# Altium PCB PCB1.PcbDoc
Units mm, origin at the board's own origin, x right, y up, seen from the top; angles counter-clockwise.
Board outline 84.33 x 62.74 mm, 2 copper layers (Top Layer, Bottom Layer); 29 components, 23 nets, 114 pads, 0 vias.
Unrouted connection lines stored in the file: 67.
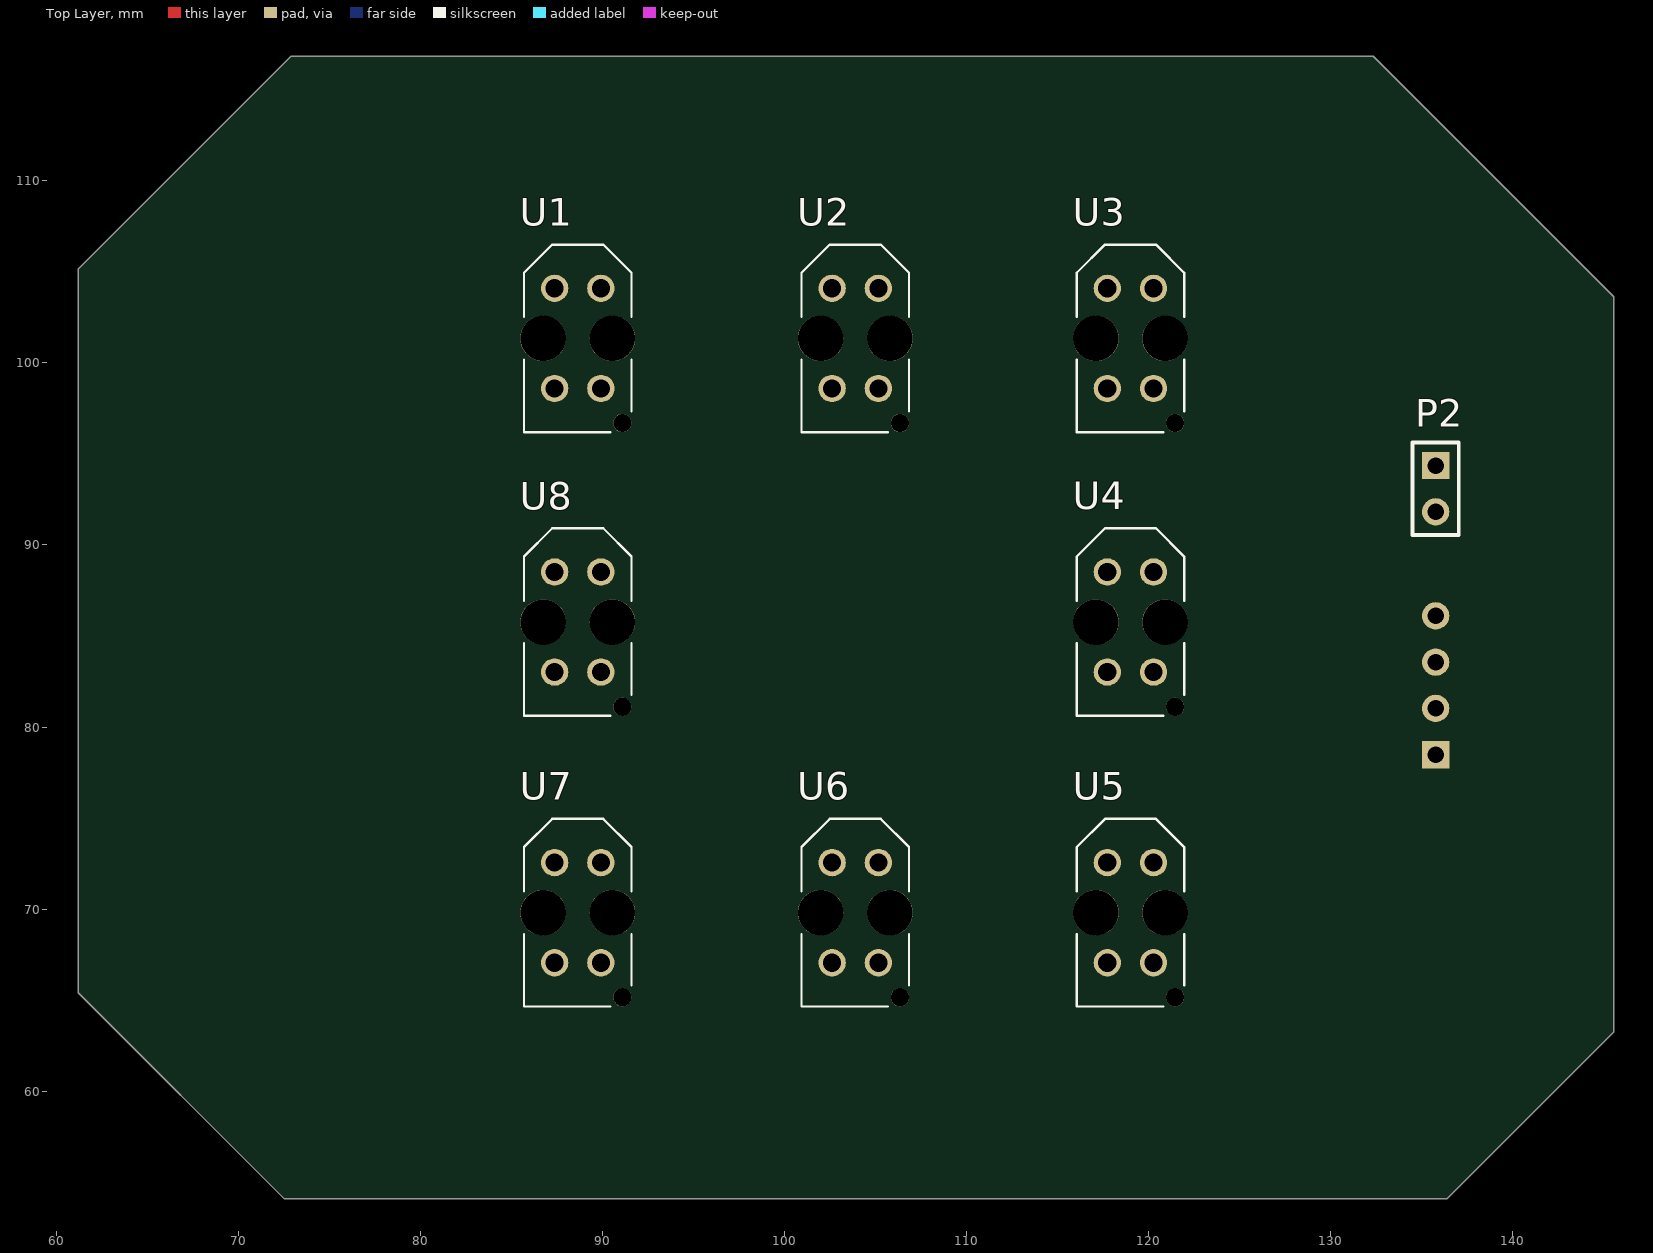
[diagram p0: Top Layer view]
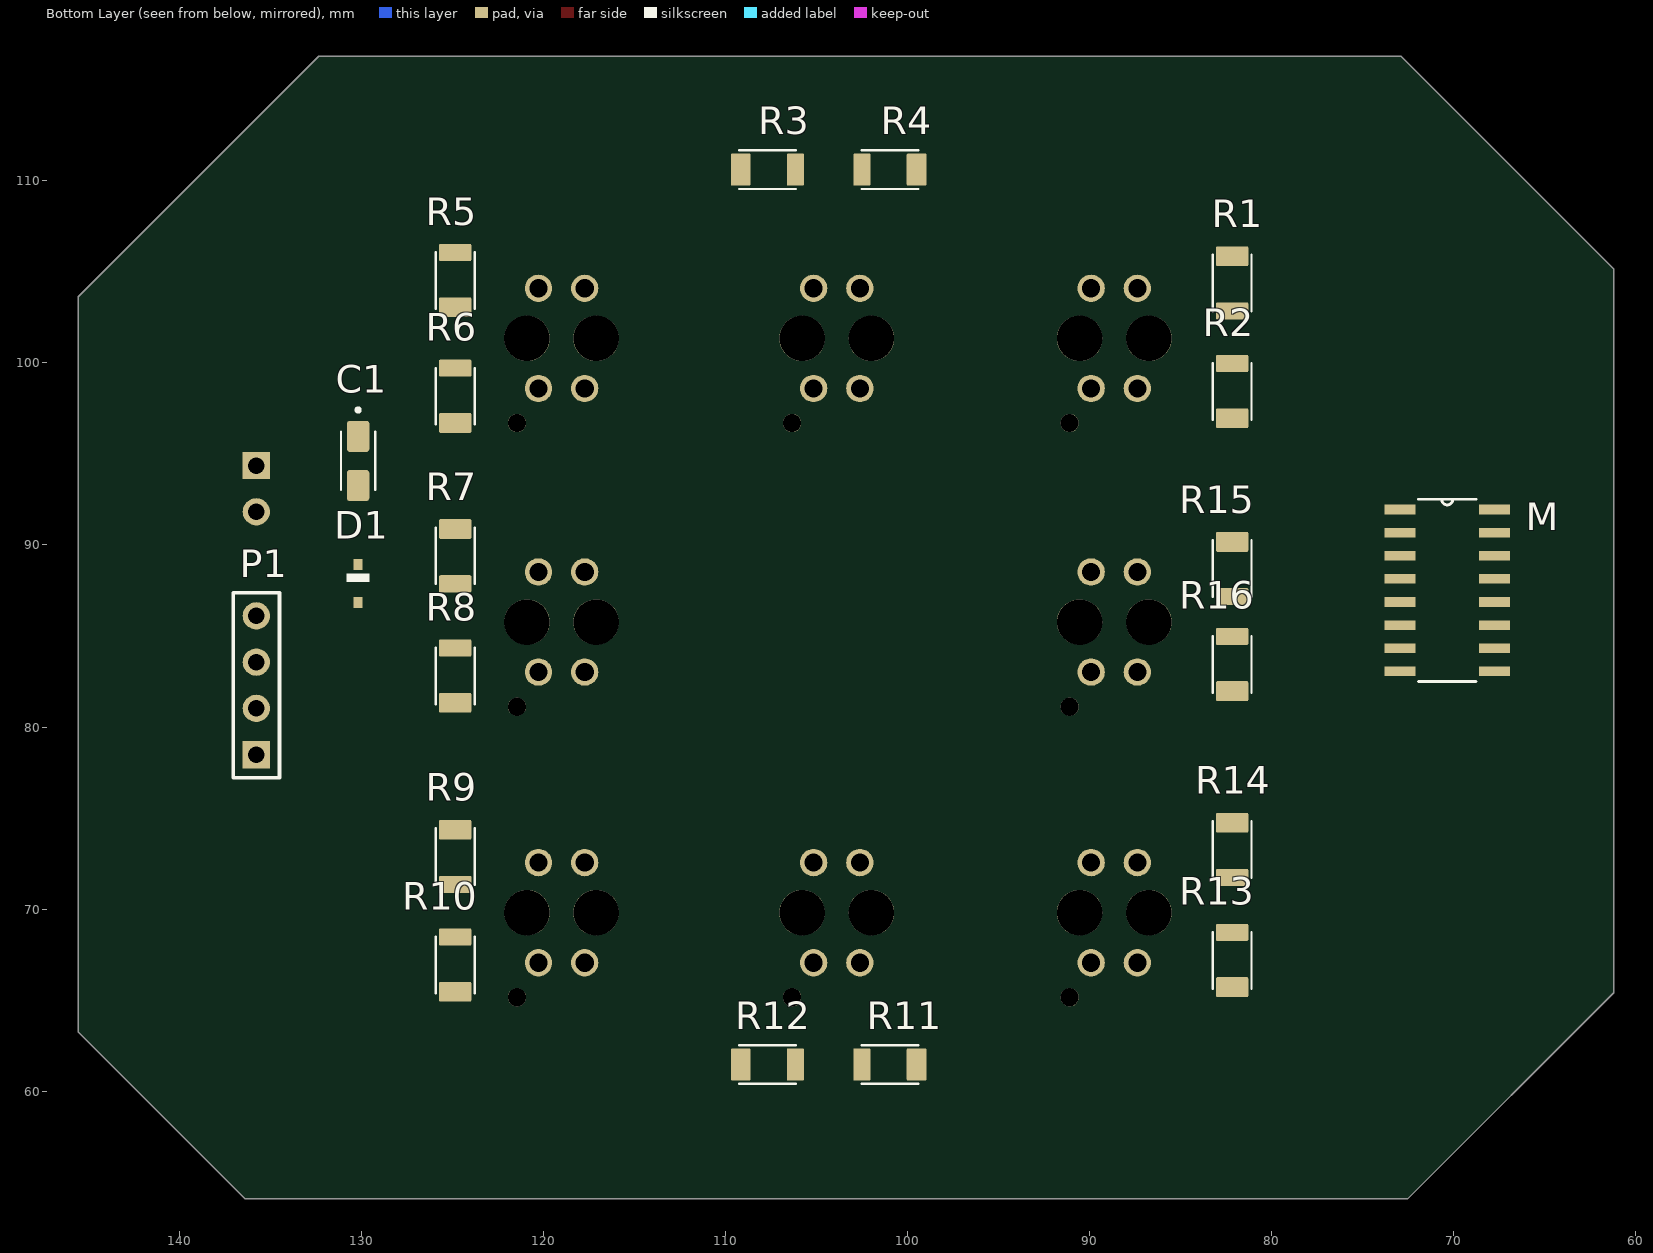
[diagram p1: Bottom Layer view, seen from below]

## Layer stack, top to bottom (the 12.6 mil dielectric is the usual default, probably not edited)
Top Solder: solder mask 0.0102, Solder Resist, Dk 3.5
Top Layer: signal copper 0.0356
Dielectric 1: dielectric 0.32, FR-4, Dk 4.8
Bottom Layer: signal copper 0.0356
Bottom Solder: solder mask 0.0102, Solder Resist, Dk 3.5

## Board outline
61.214,65.405 72.517,54.102 136.398,54.102 145.542,63.246 145.542,103.632 132.334,116.84 72.898,116.84 61.214,105.156

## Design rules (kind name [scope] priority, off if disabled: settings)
Clearance [All] p1: gap=0.254 ignorepadtopadclearanceinfootprint=FALSE except(0: Arc-Hole Track-Hole SMDPad-Hole THPad-Hole Via-Hole Fill-Hole Poly-Hole Region-Hole Text-Hole)
PolygonConnect [All] p1: connectstyle=Relief reliefconductorwidth=0.254 reliefentries=4 polygonreliefangle="90 Angle" airgapwidth=0.254
RoutingVias [All] p1: holewidth=0.711 width=1.27 viastyle="Through Hole" minholewidth=0.711 minwidth=1.27 maxholewidth=0.711 maxwidth=1.27
SolderMaskExpansion [All] p1: expansion=0.102 istentingtop=FALSE
Width [All] p1: maxlimit=0.254 minlimit=0.254 preferedwidth=0.254
30 further rules are at their usual default settings.

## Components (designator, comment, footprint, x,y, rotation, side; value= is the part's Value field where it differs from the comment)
C1 "0.1uf" CAPMP3216X180N 130.175,94.615 r270 bottom
D1 "DIOD" SOD2513X120N 130.175,87.884 r270 bottom
M "74HC4051D" SOIC127P600X175-16N 70.358,87.503 r180 bottom
P1 "A+D3" HDR1X4 135.763,78.486 r90 bottom
P2 "Header 2" HDR1X2 135.763,94.361 r270 top
R1 "220" RESC3115X65N 82.169,104.394 r270 bottom
R2 "2K" RESC3115X65N 82.169,98.425 r90 bottom
R3 "220" RESC3115X65N 107.696,110.617 r180 bottom
R4 "2K" RESC3115X65N 100.965,110.617 r0 bottom
R5 "220" RESC3115X65N 124.841,104.521 r90 bottom
R6 "2K" RESC3115X65N 124.841,98.171 r90 bottom
R7 "220" RESC3115X65N 124.841,89.408 r270 bottom
R8 "2K" RESC3115X65N 124.841,82.804 r90 bottom
R9 "220" RESC3115X65N 124.841,72.898 r270 bottom
R10 "2K" RESC3115X65N 124.841,66.929 r90 bottom
R11 "220" RESC3115X65N 100.965,61.468 r0 bottom
R12 "2K" RESC3115X65N 107.696,61.468 r180 bottom
R13 "220" RESC3115X65N 82.169,67.183 r90 bottom
R14 "2K" RESC3115X65N 82.169,73.279 r270 bottom
R15 "220" RESC3115X65N 82.169,88.705 r270 bottom
R16 "2K" RESC3115X65N 82.169,83.439 r90 bottom
U1 "IR_SENSOR" OPTO_TCRT5000 88.646,101.346 r90 top
U2 "IR_SENSOR" OPTO_TCRT5000 103.886,101.346 r90 top
U3 "IR_SENSOR" OPTO_TCRT5000 118.999,101.346 r90 top
U4 "IR_SENSOR" OPTO_TCRT5000 118.999,85.769 r90 top
U5 "IR_SENSOR" OPTO_TCRT5000 118.999,69.806 r90 top
U6 "IR_SENSOR" OPTO_TCRT5000 103.886,69.806 r90 top
U7 "IR_SENSOR" OPTO_TCRT5000 88.646,69.806 r90 top
U8 "IR_SENSOR" OPTO_TCRT5000 88.646,85.769 r90 top

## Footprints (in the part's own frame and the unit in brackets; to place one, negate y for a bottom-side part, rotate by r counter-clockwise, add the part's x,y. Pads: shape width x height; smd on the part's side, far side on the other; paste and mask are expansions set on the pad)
CAPMP3216X180N [mm]
  rrect25% 1.71x1.23 smd: 1(-1.35,0) 2(1.35,0)
  silkscreen extent -2.9,-0.93 1.6,0.93, body extent -1.6,-0.76 1.6,0.84, height 1.75
HDR1X2 [mm] "Connector; Header; 2 Position"
  rect 1.5x1.5 hole 0.9: 1(0,0)
  round 1.5 hole 0.9: 2(2.54,0)
  silkscreen extent -1.27,-1.27 3.81,1.27, body extent -1.27,-1.28 3.81,1.26, height 8.79
HDR1X4 [mm] "Connector; Header; 4 Position"
  rect 1.5x1.5 hole 0.9: 1(0,0)
  round 1.5 hole 0.9: 2(2.54,0) 3(5.08,0) 4(7.62,0)
  silkscreen extent -1.27,-1.27 8.89,1.27, body extent -1.27,-1.28 8.89,1.26, height 8.38
OPTO_TCRT5000 [mm]
  round 1.5 hole 1: A(2.75,1.27) CATH(2.75,-1.27) COLL(-2.75,1.27) E(-2.75,-1.27)
  round 1 hole 1 unplated: ""(-4.65,-2.45)
  round 2.5 hole 2.5 unplated: ""(0,1.9) ""(0,-1.9)
  silkscreen extent -5.15,-2.95 5.15,2.95, body extent -5.04,-3.4 5.16,3.4, height 7.2
RESC3115X65N [mm]
  rrect14% 1.09x1.77 smd: 1(-1.465,0)
  rrect14% 0.94x1.77 smd: 2(1.54,0)
  silkscreen extent -1.55,-1.06 1.55,1.06, body extent -1.55,-0.77 1.55,0.77, height 0.53
SOD2513X120N [mm]
  rect 0.6x0.5 smd: A(1.05,0) C(-1.05,0)
  silkscreen extent -0.53,-0.63 -0.1,0.63, body extent -1.25,-0.64 1.25,0.66, height 1.05
SOIC127P600X175-16N [mil]
  rect 67x21 smd: 1(-102,175) 2(-102,125) 3(-102,75) 4(-102,25) 5(-102,-25) 6(-102,-75) 7(-102,-125) 8(-102,-175) 9(102,-175) 10(102,-125) 11(102,-75) 12(102,-25) 13(102,25) 14(102,75) 15(102,125) 16(102,175)
  silkscreen extent -62,-197 62,197, body extent -118,-195 118,195, height 67

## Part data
C1: library part T491A475K010AT, "4.7ÂµF Molded Tantalum Capacitors 10V 1206 (3216 Metric) 5Ohm", Package="1206 AVX Corporation"
D1: library part 1N4148WS-7-F, "Diode Standard 75 V 150mA Surface Mount SOD-323", Package="SOD-323 Diodes Inc."
M: "1 Circuit IC Switch 8:1 130Ohm 16-SOIC", Package="SOIC-16 Toshiba"
P1: library part "Header 6", "Header, 6-Pin"
P2: "Header, 2-Pin"
R1 R2 R3 R4 R5 R6 R7 R8 R9 R10 R11 R12 R13 R14 R15 R16: library part 1879462-3, "RL73H 2B R12 1% 5K RL", Package=None
U1 U2 U3 U4 U5 U6 U7 U8: library part TCRT5000, "950 nm 60 mA Through Hole Reflective Optical Sensor with Transistor Output", Package=None

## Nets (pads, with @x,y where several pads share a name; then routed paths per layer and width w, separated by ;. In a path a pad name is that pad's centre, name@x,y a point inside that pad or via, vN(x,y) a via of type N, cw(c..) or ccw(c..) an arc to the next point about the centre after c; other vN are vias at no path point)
+5: C1.1 D1.C M.16 R1.2 R2.2 R3.2 R4.2 R5.2 R6.2 R7.2 R8.2 R9.2 R10.2 R11.2 R12.2 R13.2 R14.2 R15.2 R16.2
A1: M.3 P1.1
D1: M.11 P1.2
D2: M.10 P1.3
D3: M.9 P1.4
GND: C1.2 M.6 M.7 M.8 P2.1 U1.CATH U1.E U2.CATH U2.E U3.CATH U3.E U4.CATH U4.E U5.CATH U5.E U6.CATH U6.E U7.CATH U7.E U8.CATH U8.E
NetD1_A: D1.A P2.2
NetR1_1: R1.1 U1.A
NetR3_1: R3.1 U2.A
NetR5_1: R5.1 U3.A
NetR7_1: R7.1 U4.A
NetR9_1: R9.1 U5.A
NetR11_1: R11.1 U6.A
NetR13_1: R13.1 U7.A
NetR15_1: R15.1 U8.A
S1: M.13 R2.1 U1.COLL
S2: M.14 R4.1 U2.COLL
S3: M.15 R6.1 U3.COLL
S4: M.12 R8.1 U4.COLL
S5: M.1 R10.1 U5.COLL
S6: M.5 R12.1 U6.COLL
S7: M.2 R14.1 U7.COLL
S8: M.4 R16.1 U8.COLL
pads on no net: U1. U2. U3. U4. U5. U6. U7. U8.

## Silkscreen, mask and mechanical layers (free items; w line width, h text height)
Mechanical 1:
  the board outline again, w0.254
